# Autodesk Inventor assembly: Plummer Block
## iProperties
Created: 2002-02
Part Number: Plummer Block
Document SubType Name: Assembly
Designer: ***
Control State: 0
Master: False
Checked Out: False
Shininess: 64.0
Length Units: 11269
Angle Units: 11279
Time Units: 11290
Mass Units: 11283
Length Display Precision: 3
Angle Display Precision: 2
Density: 0.0
Volumn: 0.0
Area: 0.0
PropertySet Name: Model Information
Author: ***
